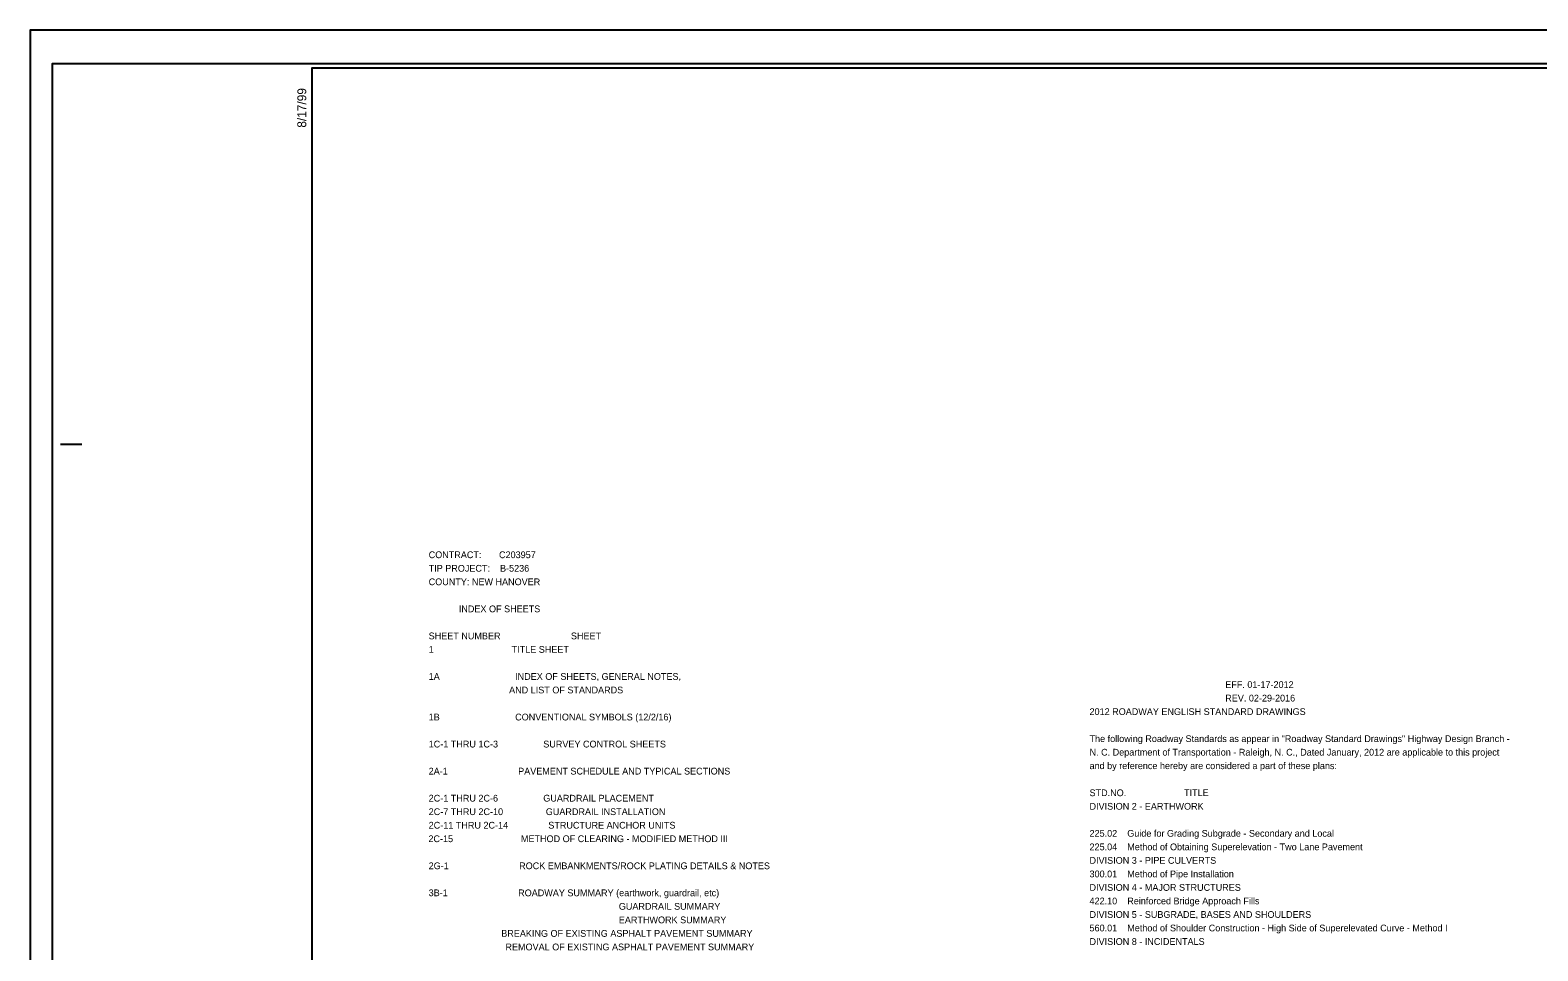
# Model space of a CAD drawing. Extents: x 9834 to 11517, y 9978 to 11072.
# Drawn here: x 9834 to 10725, y 10528 to 11072 of the extents above; entities that cross this region are included whole.
import ezdxf

# ---------------------------------------------------------------- set-up
doc = ezdxf.new("R2010")
doc.units = 0
for name, color, linetype in [('Default', 7, 'Continuous'), ('Sheet Cutting Line CELL', 7, 'Continuous'), ('Sheet Plan CELL', 7, 'Continuous'), ('Sheet Plot Border Inside CELL', 7, 'Continuous'), ('Sheet Plot Border Outside CELL', 7, 'Continuous')]:
    doc.layers.add(name, color=color, linetype=linetype)

msp = doc.modelspace()

# ---------------------------------------------------------------- linework, layer by layer
at = {"layer": 'Sheet Cutting Line CELL'}
for p, q in [((11517, 11072.5), (9833.5, 11072.5)), ((9833.5, 11072.5), (9833.5, 9977.5))]:
    msp.add_line(p, q, dxfattribs=at)
at = {"layer": 'Sheet Plan CELL'}
for p, q in [((10000, 11050), (10000, 11050)), ((9851.5, 10827.5), (9864, 10827.5))]:
    msp.add_line(p, q, dxfattribs=at)
msp.add_lwpolyline([(11500, 11050), (10000, 11050), (10000, 10000), (11500, 10000)], close=True, dxfattribs=at)
at = {"layer": 'Sheet Plot Border Inside CELL'}
msp.add_lwpolyline([(9846.5, 9997.5), (11512.5, 9997.5), (11512.5, 11052.5), (9846.5, 11052.5)], close=True, dxfattribs=at)
at = {"layer": 'Sheet Plot Border Outside CELL'}
msp.add_lwpolyline([(9833.5, 9977.5), (11517, 9977.5), (11517, 11072.5), (9833.5, 11072.5)], close=True, dxfattribs=at)

# ---------------------------------------------------------------- texts
at = {"layer": 'Default'}
for s, p in [('CONTRACT:       C203957                 ', (10069.15, 10760.13)), ('TIP PROJECT:    B-5236                  ', (10069.15, 10752.13)), ('COUNTY: NEW HANOVER                     ', (10069.15, 10744.13)), ('            INDEX OF SHEETS                             ', (10069.15, 10728.13)), ('SHEET NUMBER                            SHEET', (10069.15, 10712.13)), ('1                               TITLE SHEET', (10069.15, 10704.13)), ('1A                              INDEX OF SHEETS, GENERAL NOTES,', (10069.15, 10688.13)), ('                                AND LIST OF STANDARDS', (10069.15, 10680.13)), ('                                                      EFF. 01-17-2012', (10459.92, 10683.33)), ('2012 ROADWAY ENGLISH STANDARD DRAWINGS', (10459.92, 10667.33)), ('                                                      REV. 02-29-2016', (10459.92, 10675.33)), ('1B                              CONVENTIONAL SYMBOLS (12/2/16)', (10069.15, 10664.13)), ('The following Roadway Standards as appear in "Roadway Standard Drawings" Highway Design Branch -', (10459.92, 10651.33)), ('1C-1 THRU 1C-3                  SURVEY CONTROL SHEETS', (10069.15, 10648.13)), ('N. C. Department of Transportation - Raleigh, N. C., Dated January, 2012 are applicable to this project', (10459.92, 10643.33)), ('2A-1                            PAVEMENT SCHEDULE AND TYPICAL SECTIONS', (10069.15, 10632.13)), ('and by reference hereby are considered a part of these plans:', (10459.92, 10635.33)), ('2C-1 THRU 2C-6                  GUARDRAIL PLACEMENT', (10069.15, 10616.13)), ('STD.NO.                       TITLE', (10459.92, 10619.33)), ('2C-7 THRU 2C-10                 GUARDRAIL INSTALLATION', (10069.15, 10608.13)), ('DIVISION 2 - EARTHWORK', (10459.92, 10611.33)), ('2C-11 THRU 2C-14                STRUCTURE ANCHOR UNITS', (10069.15, 10600.13)), ('2C-15                           METHOD OF CLEARING - MODIFIED METHOD III', (10069.01, 10592.13)), ('225.02    Guide for Grading Subgrade - Secondary and Local', (10459.92, 10595.33)), ('225.04    Method of Obtaining Superelevation - Two Lane Pavement', (10459.92, 10587.33)), ('DIVISION 3 - PIPE CULVERTS', (10459.92, 10579.33)), ('2G-1                            ROCK EMBANKMENTS/ROCK PLATING DETAILS & NOTES', (10069.14, 10576.13)), ('300.01    Method of Pipe Installation ', (10459.92, 10571.33)), ('DIVISION 4 - MAJOR STRUCTURES', (10459.92, 10563.33)), ('3B-1                            ROADWAY SUMMARY (earthwork, guardrail, etc)', (10069.14, 10560.13)), ('      GUARDRAIL SUMMARY', (10172.66, 10552.13)), ('422.10    Reinforced Bridge Approach Fills', (10459.92, 10555.33)), ('      EARTHWORK SUMMARY', (10172.66, 10544.13)), ('DIVISION 5 - SUBGRADE, BASES AND SHOULDERS', (10459.92, 10547.33)), ('                                  BREAKING OF EXISTING ASPHALT PAVEMENT SUMMARY', (10061.55, 10536.13)), ('560.01    Method of Shoulder Construction - High Side of Superelevated Curve - Method I', (10459.92, 10539.33)), ('                                 REMOVAL OF EXISTING ASPHALT PAVEMENT SUMMARY', (10065.51, 10528.13)), ('DIVISION 8 - INCIDENTALS', (10459.92, 10531.33))]:
    msp.add_text(s, height=4, dxfattribs=at).set_placement(p)
at = {"layer": 'Sheet Plan CELL'}
msp.add_text('8/17/99', height=5.25, rotation=90, dxfattribs=at).set_placement((9996.75, 11014.8))

doc.saveas('drawing.dxf')
